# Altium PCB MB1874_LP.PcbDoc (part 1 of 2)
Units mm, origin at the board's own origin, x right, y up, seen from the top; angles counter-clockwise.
Board outline 59.8 x 34.35 mm, 2 copper layers (Top Layer, Bottom Layer), stack 0.78 mm thick; 77 components, 63 nets, 242 pads, 939 vias.
Unrouted connection lines stored in the file: 1.
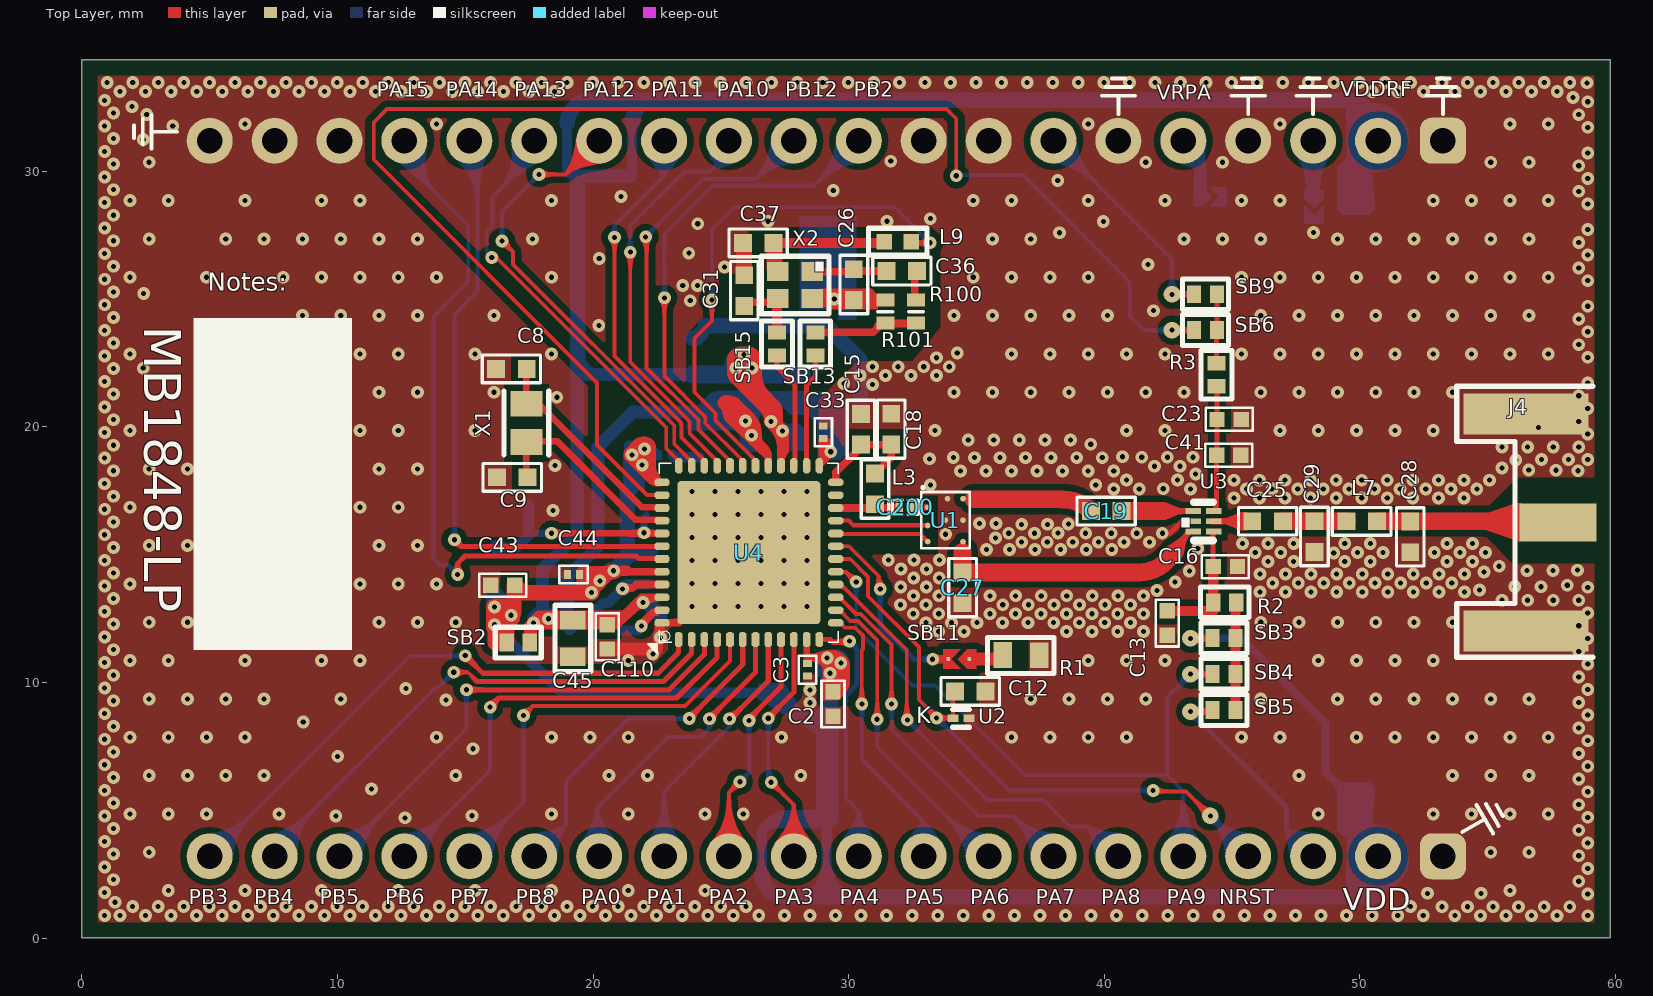
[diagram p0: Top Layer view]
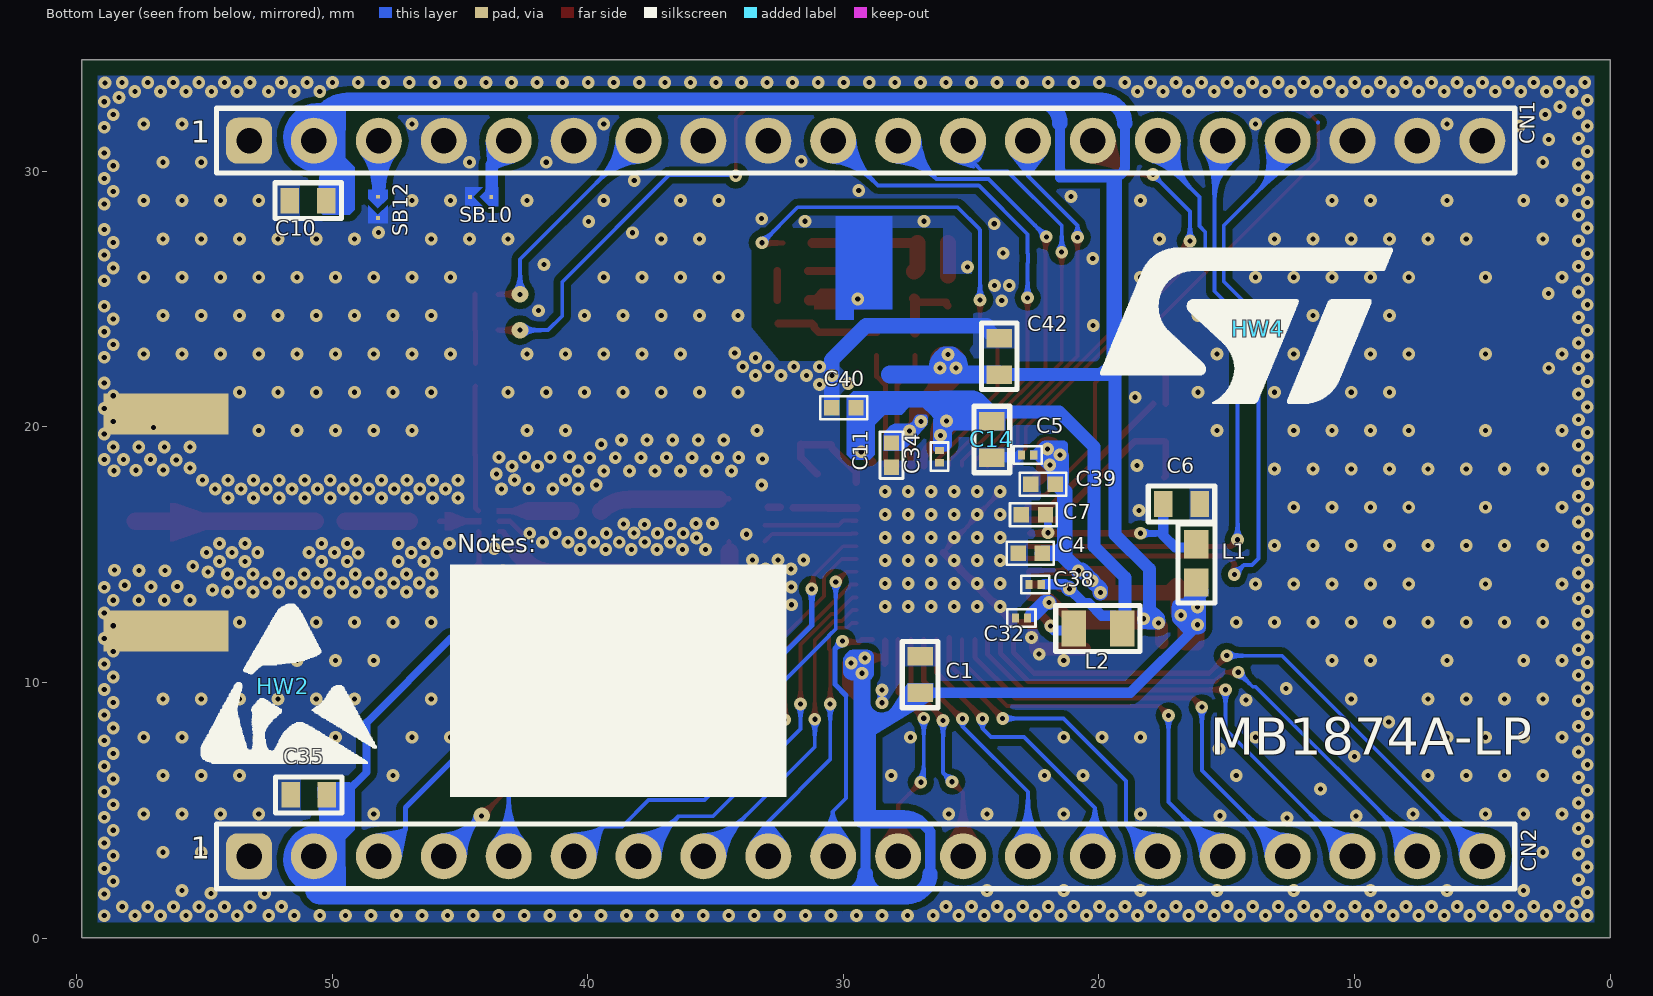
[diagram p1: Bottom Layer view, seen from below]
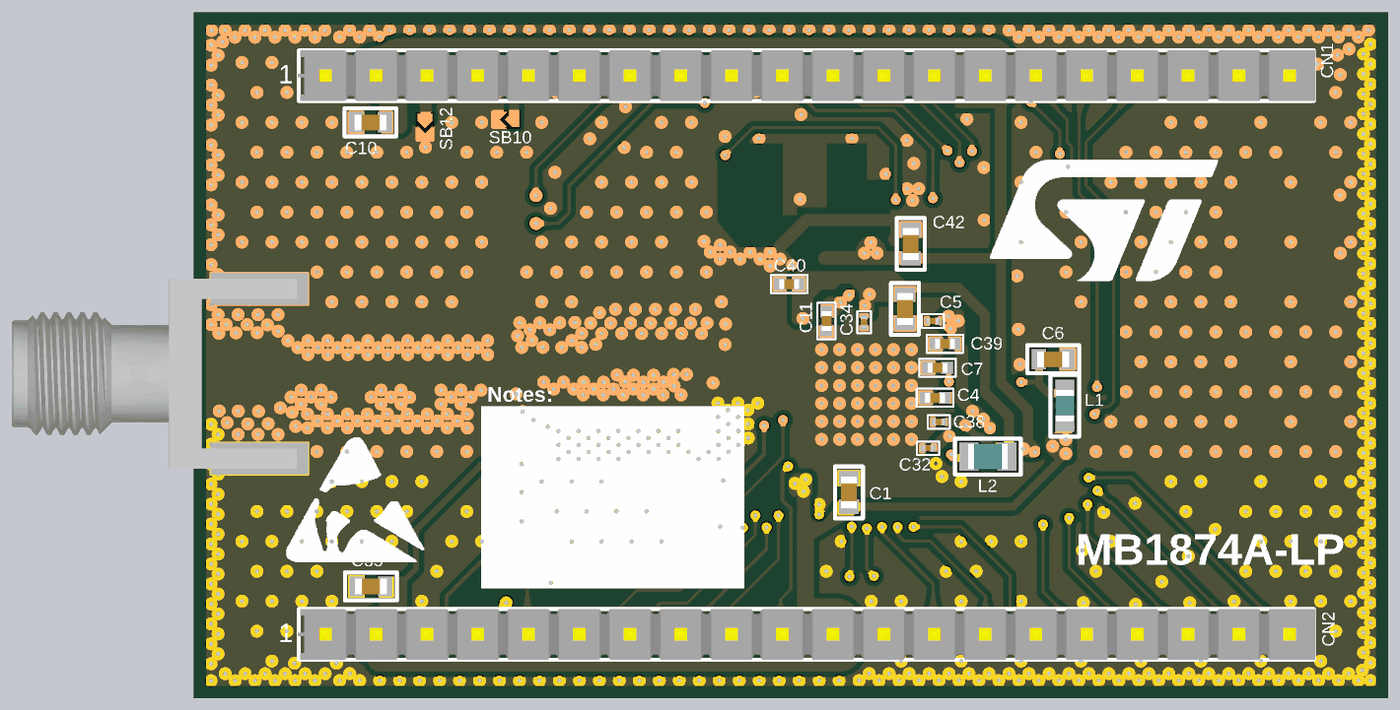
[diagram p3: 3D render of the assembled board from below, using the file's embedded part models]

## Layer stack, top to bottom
Top Solder: solder mask 0.03, Solder Resist, Dk 3.5
Top Layer: signal copper 0.035
Dielectric 1: core 0.71, FR-4, Dk 5
Bottom Layer: signal copper 0.035
Bottom Solder: solder mask 0.03, Solder Resist, Dk 3.5

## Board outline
0,0.009 0,34.363 59.8,34.363 59.8,0.009

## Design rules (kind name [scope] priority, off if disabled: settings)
BoardOutlineClearance [All and not (InComponent('J4', 'Target') or IsText)] p1: gap=0.6 ignorepadtopadclearanceinfootprint=FALSE
Clearance Clearance_Keepout [IsKeepout] p1: gap=0 ignorepadtopadclearanceinfootprint=FALSE
Clearance Clearance_GND_50ohm [InNetClass('50Ohm') vs InNamedPolygon('TOP_LAYER_GND')] p2: gap=0.25 ignorepadtopadclearanceinfootprint=FALSE except(0: Arc-Hole Track-Hole SMDPad-Hole THPad-Hole Via-Hole Fill-Hole Poly-Hole Region-Hole Text-Hole; 0.24: Arc-Fill Arc-Poly Arc-Region Track-Fill Track-Poly Track-Region)
Clearance Clearance_tab [(ObjectKind = 'Pad') And (Name Like 'Tab*-*') vs OnLayer('Keep-Out Layer')] p3: gap=0 ignorepadtopadclearanceinfootprint=FALSE
Clearance Clearance_Via_to_pad [IsVia vs IsPad] p4: gap=0.15 ignorepadtopadclearanceinfootprint=FALSE except(0: Arc-Hole Track-Hole SMDPad-Hole THPad-Hole Via-Hole Fill-Hole Poly-Hole Region-Hole Text-Hole)
Clearance Clearance_via_to_via [(ObjectKind = 'Via') And (Net <> 'GND') vs (ObjectKind = 'Via') And (Net <> 'GND')] p5: gap=0.25 ignorepadtopadclearanceinfootprint=FALSE except(0: Arc-Hole Track-Hole SMDPad-Hole THPad-Hole Via-Hole Fill-Hole Poly-Hole Region-Hole Text-Hole)
Clearance "Clearance_Polygon to All" [InPolygon] p6: gap=0.25 ignorepadtopadclearanceinfootprint=FALSE except(0: Arc-Hole Track-Hole SMDPad-Hole THPad-Hole Via-Hole Fill-Hole Poly-Hole Region-Hole Text-Hole)
Clearance [All] p7: gap=0.1 ignorepadtopadclearanceinfootprint=FALSE except(0: Arc-Hole Track-Hole SMDPad-Hole THPad-Hole Via-Hole Fill-Hole Poly-Hole Region-Hole Text-Hole)
ComponentClearance [All] p1 off: gap=0 collisioncheckmode=3 verticalgap=0.1 showdistances=FALSE
DiffPairsRouting [InDifferentialPair('RFI')] p1: maxlimit=0.1 minlimit=0.1 mostfreqgap=0.1 toplayer_minwidth=0.164 toplayer_maxwidth=0.164 toplayer_prefwidth=0.164 bottomlayer_minwidth=0.164 bottomlayer_maxwidth=0.164 bottomlayer_prefwidth=0.164 maxuncoupledlength=12.7
HoleSize [All] p1: absolutevalues=TRUE maxlimit=10 minlimit=0.025 maxpercent=80.000 minpercent=20.000
HoleToHoleClearance [All] p1: gap=0.25 allowstackedmicrovias=TRUE
MaximumViaCount MaximumViaCount_5 [InNet('GND')] p1: limit=1300
MaximumViaCount MaximumViaCount_4 [InNet('VDDRF1V55')] p2: limit=1000
MaximumViaCount MaximumViaCount_3 [InNet('VDDPA')] p3: limit=1000
MaximumViaCount MaximumViaCount_2 [InNet('VDDRF')] p4: limit=1000
MaximumViaCount MaximumViaCount_1 [InNet('VDD')] p5: limit=1000
MaximumViaCount [All] p6: limit=3
MinimumSolderMaskSliver [All] p1: minsoldermaskwidth=0.1
NetAntennae [All] p1 off: netantennaetolerance=0
PlaneConnect [InNet('GND')] p1: planeconnectstyle=Relief reliefexpansion=0.508 reliefentries=4 reliefconductorwidth=0.21 reliefairgap=0.21
PolygonConnect PolygonConnect_GND [InNet('GND') and not InComponent('J4')] p1: connectstyle=Direct reliefconductorwidth=0.254 reliefentries=4 polygonreliefangle="90 Angle" airgapwidth=0.254
PolygonConnect PolygonConnect_U1 [InComponent('U1')] p2: connectstyle=Direct reliefconductorwidth=0.254 reliefentries=4 polygonreliefangle="90 Angle" airgapwidth=0.254
PolygonConnect PolygonConnect_6 [InNet('VDDRF1V55')] p3: connectstyle=Direct reliefconductorwidth=0.254 reliefentries=4 polygonreliefangle="90 Angle" airgapwidth=0.254
PolygonConnect PolygonConnect_5 [InNet('VDDRF1V55')] p4: connectstyle=Direct reliefconductorwidth=0.254 reliefentries=4 polygonreliefangle="90 Angle" airgapwidth=0.254
PolygonConnect PolygonConnect_4 [InNet('vDDRF')] p5: connectstyle=Direct reliefconductorwidth=0.254 reliefentries=4 polygonreliefangle="90 Angle" airgapwidth=0.254
PolygonConnect PolygonConnect_3 [InNet('VDDPA')] p6: connectstyle=Direct reliefconductorwidth=0.254 reliefentries=4 polygonreliefangle="90 Angle" airgapwidth=0.254
PolygonConnect PolygonConnect_1 [InNet('VDDRF1V55')] p7: connectstyle=Direct reliefconductorwidth=0.254 reliefentries=4 polygonreliefangle="90 Angle" airgapwidth=0.254
PolygonConnect [InNet('VDD')] p8: connectstyle=Direct reliefconductorwidth=0.254 reliefentries=4 polygonreliefangle="90 Angle" airgapwidth=0.254
PolygonConnect PolygonConnect_All [All] p9: connectstyle=Relief reliefconductorwidth=0.254 reliefentries=4 polygonreliefangle="45 Angle" airgapwidth=0.254
RoutingLayers "RoutingLayers_90 Ohms" [InDifferentialPairClass('All Differential Pairs')] p1: top layer_v5=TRUE bottom layer_v5=TRUE
RoutingLayers [All] p2: top layer_v5=TRUE bottom layer_v5=TRUE
RoutingVias RoutingVias_BGA [InDrillLayerPair('Top Layer - MidLayer 1')] p1: holewidth=0.125 width=0.25 viastyle="Through Hole" minholewidth=0.125 minwidth=0.25 maxholewidth=0.125 maxwidth=0.3
RoutingVias [All] p2: holewidth=0.2 width=0.65 viastyle="Through Hole" minholewidth=0.2 minwidth=0.5 maxholewidth=0.2 maxwidth=0.7
ShortCircuit ShortCircuit_1 [IsPad and (Name = 'J4-2') vs IsVia and InNet('GND')] p1: allowed=TRUE
ShortCircuit ShortCircuit_U4 [IsPad and (Name = 'U4-49') vs IsVia and InNet('GND')] p2: allowed=TRUE
ShortCircuit [(ObjectKind = 'Via') And (DrillPair = 'Top Layer - MidLayer 1') vs Ispad] p3: allowed=TRUE
SilkToSilkClearance [All] p1: silktosilkclearance=0.08
SilkToSolderMaskClearance [IsPad] p1: minsilkscreentomaskgap=0.05 clearancetoexposedcopper=TRUE
SolderMaskExpansion SolderMaskExpansion_VIA [IsVia] p1: expansion=-0.2 istentingtop=FALSE
SolderMaskExpansion [All] p2: expansion=0.075 istentingtop=FALSE
Width Width_50Ohms [InNetClass('50Ohm')] p1: maxlimit=0.7 minlimit=0.2 preferedwidth=0.7 minimp=50.000000 maximp=50.000000 favimp=50.000000
Width [All] p2: maxlimit=1.5 minlimit=0.1 preferedwidth=0.15 minimp=50.000000 maximp=50.000000 favimp=50.000000
19 further rules are at their usual default settings.

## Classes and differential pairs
component class MB1874A: C1 C2 C3 C4 C5 C6 C7 C8 C9 C10 C11 C12 C13 C14 C15 C16 C18 C19 C23 C25 C26 C27 C28 C29 C31 C32 C33 C34 C35 C36 C37 C38 C39 C40 C41 C42 C43 C44 C45 C110 CN1 CN2 J4 L1 L2 L3 L7 L9 R1 R2 R3 R100 R101 S1 SB2 SB3 SB4 SB5 SB6 SB9 SB10 SB11 SB12 SB13 SB15 U2 U3 U4 X1 X2
net class 50ohm: NetC19_1 NetC19_2 NetC25_1 NetC25_2 NetC27_2 NetC28_1
differential pair RFI: +RFI_P -RFI_N

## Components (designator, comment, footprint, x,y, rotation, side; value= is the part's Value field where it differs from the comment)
C1 "" CAPC1608X09N 26.998,10.311 r270 bottom
C2 "" CAPC1005X06N 29.391,9.159 r90 top
C3 "" 0201 28.391,10.259 r90 top
C4 "" CAPC1005X06N 22.691,15.059 r180 bottom
C5 "" 0201 23.034,18.898 r180 bottom
C6 "" CAPC1608X09N 16.771,16.986 r180 bottom
C7 "" CAPC1005X06N 22.566,16.559 r0 bottom
C8 "Capacitor" 0402 17.405,22.273 r180 top
C9 "Capacitor" 0402 17.44,18.03 r180 top
C10 "" CAPC1608X09N 50.949,28.855 r0 bottom
C11 "" CAPC1005X06N 28.12,18.9 r270 bottom
C12 "" 0402 34.165,9.65 r0 top
C13 "" CAPC1005X06N 42.469,12.326 r90 top
C14 "" CAPC1608X09N 24.191,19.509 r270 bottom
C15 "" 0402 30.487,19.309 r90 top
C16 "" CAPC1005X06N 44.742,14.537 r180 top
C18 "" 0402 31.672,20.514 r270 top
C19 "" 0402 40.678,16.709 r180 top
C23 "" CAPC1005X06N 44.893,20.293 r180 top
C25 "" 0402_2 45.764,16.309 r0 top
C26 "Capacitor" 0402 30.205,26.171 r270 top
C27 "NC" 0402_2 34.464,13.078 r90 top
C28 "MCD-00102" 0402 51.979,16.294 r270 top
C29 "MCD-00102" 0402 48.226,16.309 r270 top
C31 "Capacitor" 0402 25.918,24.738 r90 top
C32 "" 0201 23.273,12.523 r180 bottom
C33 "" 0201 29.01,20.032 r270 top
C34 "" 0201 26.239,18.601 r90 bottom
C35 "" CAPC1608X09N 50.923,5.601 r180 bottom
C36 "" 0402 32.683,26.1 r180 top
C37 "" 0402 25.865,27.2 r0 top
C38 "" 0201 22.26,13.84 r0 bottom
C39 "" CAPC1005X06N 22.191,17.759 r0 bottom
C40 "" CAPC1005X06N 29.987,20.756 r0 bottom
C41 "" CAPC1005X06N 44.878,18.893 r0 top
C42 "" CAPC1608X09N 23.904,22.761 r90 bottom
C43 "" CAPC1005X06N 16.468,13.811 r0 top
C44 "" 0201 18.997,14.231 r0 top
C45 "" CAPC1608X09N 19.211,11.724 r270 top
C110 "" CAPC1005X06N 20.561,11.788 r270 top
C200 "MCD-00198" 0201 32.463,16.857 r180 top
CN1 "CON20" CO_SAMTEC_TSW-120-07-X-S 29.13,31.2 r180 bottom
CN2 "CON20" CO_SAMTEC_TSW-120-07-X-S 29.13,3.2 r180 bottom
Designator16 "Comment" IMPEDANCE_TABLE 100.43,-31.664 r0 top
HW2 "Logo" LOGO_MAIN 51.913,9.844 r180 bottom
HW4 "Logo" LOGO_ST 13.76,23.849 r180 bottom
J4 "SMA_T_9.52_NF" SMA_AMPHENOL_50ohms_Edge_PCB 59.264,16.261 r90 top
L1 "" INDC1608X95N 16.191,14.659 r90 bottom
L2 "" INDC2012X13N 20.041,12.109 r0 bottom
L3 "" 0402_COIL 31.037,17.573 r270 top
L7 "" 0402_COIL 50.079,16.309 r0 top
L9 "ferrite" IND_MURATA_LQW15A 31.93,27.25 r0 top
R1 "" RESC1608X05N 36.741,11.059 r180 top
R2 "" RESC1005X04N 44.72,13.138 r0 top
R3 "" RESC1005X04N 44.398,22.043 r90 top
R100 "Resistor" R0402 32.641,24.509 r90 top
R101 "Resistor" R0402 31.441,24.509 r90 top
SB2 "Close" SB_0402 17.075,11.561 r180 top
SB3 "Close" SB_0402 44.688,11.737 r0 top
SB4 "Open" SB_0402 44.688,10.337 r0 top
SB5 "Open" SB_0402 44.688,8.923 r0 top
SB6 "Close" SB_0402 43.961,23.794 r0 top
SB9 "Open" SB_0402 43.961,25.194 r0 top
SB10 "Open" GC_0402 44.158,29.005 r0 bottom
SB11 "Close" GC_0402 34.35,10.919 r180 top
SB12 "Open" GC_0402 48.216,28.631 r270 bottom
SB13 "Close" SB_0402 28.7,23.25 r90 top
SB15 "Close" SB_0402 27.2,23.25 r90 top
Target "" "Target PCB" -9,-9 r90 top
Target "" "Target PCB" 74,17.2 r90 top
Target "" "Target PCB" -9,43 r90 top
U1 "IPD STM STM32WL" "IPD STM" 33.788,16.354 r180 top
U2 "" DIOM0603X03N 34.4,8.6 r0 top
U3 "BGS12SN6" SON40P70X40-6N 43.884,16.309 r0 top
U4 "STM32WLxx_QFN48" STM32WLXX_QFN48 26.097,15.083 r90 top
X1 "XTAL_2_PINS" OSC_NDK_NX2012SA 17.395,20.162 r90 top
X2 "" OSC_NDK_NX2016SA 27.91,25.553 r180 top

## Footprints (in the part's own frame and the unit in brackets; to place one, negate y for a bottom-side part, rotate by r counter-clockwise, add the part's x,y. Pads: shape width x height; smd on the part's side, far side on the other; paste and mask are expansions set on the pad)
0201 [mm]
  rect 0.28x0.35 smd: 1(0,0) 2(0.48,0)
  silkscreen extent -0.31,-0.34 0.79,0.34, body extent -0.06,-0.15 0.54,0.15, height 0.3
0402 [mm] "Chip Capacitor, Body 1.0x0.5mm, IPC High Density"
  rect 0.7x0.7 smd: 1(-0.001,0) 2(1.197,0)
  silkscreen extent -0.54,-0.54 1.74,0.54, body extent -0.42,-0.36 1.62,0.36, height 0.82
0402_2 [mm]
  rect 0.7x0.7 smd: 1(0.035,0) 2(1.233,0)
  silkscreen extent -0.51,-0.54 1.78,0.54, body extent -0.38,-0.36 1.65,0.36, height 0.82
0402_COIL [mm] "Coil FootPrint 0402"
  rect 0.7x0.7 smd: 1(-0.599,0) 2(0.599,0)
  silkscreen extent -1.15,-0.54 1.14,0.54, body extent -0.5,-0.3 0.5,0.3, height 0.51
CAPC1005X06N [mm]
  rect 0.6x0.6 smd: 1(-0.475,0) 2(0.475,0)
  silkscreen extent -0.92,-0.45 0.92,0.45, body extent -0.5,-0.25 0.5,0.25, height 0.6
CAPC1608X09N [mm]
  rect 0.725x1 smd: 1(-0.713,0) 2(0.713,0)
  Top Layer pour cut-out: -0.3,0.7 0.3,0.7 0.3,-0.7 -0.3,-0.7
  silkscreen extent -1.3,-0.7 1.3,0.7, body extent -0.8,-0.4 0.8,0.4, height 0.9
CO_SAMTEC_TSW-120-07-X-S [mm] "Header, 20-Leads, 50.80x2.54x10.80mm, Pitch 2.54mm"
  rrect50% 1.8x1.8 hole 1: 1(-24.13,0)
  round 1.8 hole 1: 2(-21.59,0) 3(-19.05,0) 4(-16.51,0) 5(-13.97,0) 6(-11.43,0) 7(-8.89,0) 8(-6.35,0) 9(-3.81,0) 10(-1.27,0) 11(1.27,0) 12(3.81,0) 13(6.35,0) 14(8.89,0) 15(11.43,0) 16(13.97,0) 17(16.51,0) 18(19.05,0) 19(21.59,0) 20(24.13,0)
  silkscreen extent -25.4,-1.27 25.4,1.27, body extent -25.46,-1.27 25.46,1.27, height 8.38
DIOM0603X03N [mm] "Molded Diode, 2-Leads, Body 0.60x0.30mm"
  rect 0.425x0.3 smd: 1(-0.312,0) 2(0.313,0)
  silkscreen extent -0.32,-0.35 0.33,0.35, body extent -0.32,-0.18 0.33,0.18, height 0.33
GC_0402 [mm] "Grain de café format 0402"
  rect 0.15x0.15 smd paste-1: 1(-0.375,0) 2(0.45,0)
  Top Layer region: -0.05,0.375 0.65,0.375 0.65,-0.375 -0.05,-0.375 0.325,0
  Top Layer region: -0.65,0.375 -0.3,0.375 0.075,0 -0.3,-0.375 -0.65,-0.375
  body extent -0.5,-0.25 0.6,0.25, height 0.2
IMPEDANCE_TABLE [mm]
IND_MURATA_LQW15A [mm] "Inductor 2-Leads,Body 1.10x0.70x0.60mm(max)"
  rect 0.6x0.6 smd: 1(-0.53,0) 2(0.53,0)
  silkscreen extent -1.14,-0.53 1.14,0.53, body extent -0.5,-0.3 0.5,0.3, height 0.51
INDC1608X95N [mm] "Chip Inductor, 2-Leads, Body 1.75x0.95x0.95mm (0603)"
  rect 1.1x0.95 smd: 1(-0.75,0) 2(0.75,0)
  silkscreen extent -1.55,-0.72 1.55,0.72, body extent -0.8,-0.48 0.8,0.47, height 0.8
INDC2012X13N [mm] "Chip Inductor, 2-Leads, Body 2.0x1.2x1.3 (0805)"
  rect 0.96x1.4 smd: 1(-0.952,0) 2(0.952,0)
  silkscreen extent -1.65,-0.9 1.65,0.9, body extent -1,-0.65 1,0.65, height 1.18
"IPD STM" [mm] "IPD STM STM32WL, Body 2.20 x 1.90 x 0.710 mm (LxWxH max)"
  round 0.22 smd mask+0.05: 1(0.69,-0.5) 2(0.69,0.84) 3(0.69,0.21) 4(-0.69,0.84) 5(-0.69,0) 6(-0.69,-0.84) 7(-0.085,-0.84) 8(0,0)
  silkscreen extent -0.95,-1.33 0.95,1.1, body extent -0.84,-1 0.84,1, height 0.71
LOGO_MAIN [mm]
  silkscreen extent -3.24,-3.02 3.65,3.22
LOGO_ST [mm]
  silkscreen extent -6.18,-2.95 5.25,3.14
OSC_NDK_NX2012SA [mm] "Crystal, 2-Leads, Body 2.05x1.20x0.55mm (Tol:-/+0.05)"
  rect 1x1.25 smd: 1(-0.75,0) 2(0.75,0)
  silkscreen extent -1.25,-0.87 1.25,0.87, body extent -1.04,-0.63 1.03,0.63, height 0.55
OSC_NDK_NX2016SA [mm] "Crystal, 4-Leads, Body 2.10x1.61x0.50mm (max), Pitch 1.35x1.05mm"
  rect 0.85x0.75 smd: 1(-0.675,-0.525) 2(0.675,-0.525) 3(0.675,0.525) 4(-0.675,0.525)
  silkscreen extent -1.33,-1.12 1.33,1.13, body extent -1,-0.8 1,0.8, height 0.5
R0402 [mm]
  rect 0.51x0.7 smd mask+0.05: 1(-0.45,0) 2(0.45,0)
  silkscreen extent 0,-0.3 0,0.3, body extent -0.52,-0.3 0.52,0.3, height 0.4
RESC1005X04N [mm] "Chip Resistor, 2-Leads, Body 1.00x0.50mm (0402)"
  rect 0.55x0.7 smd: 1(-0.45,0) 2(0.45,0)
  silkscreen extent -0.95,-0.6 0.95,0.6, body extent -0.5,-0.25 0.5,0.25, height 0.35
RESC1608X05N [mm] "Chip Resistor, 2-Leads, Body 1.60x0.80mm (0603)"
  rect 0.725x1 smd: 1(-0.713,0) 2(0.712,-0.016)
  Top Layer pour cut-out: -0.3,0.7 0.3,0.7 0.3,-0.7 -0.3,-0.7
  silkscreen extent -1.3,-0.7 1.3,0.7, body extent -0.77,-0.42 0.78,0.43, height 0.45
SB_0402 [mm]
  rect 0.55x0.7 smd: 1(-0.45,0) 2(0.45,0)
  silkscreen extent -0.9,-0.6 0.9,0.6, body extent -0.5,-0.25 0.5,0.25, height 0.25
SMA_AMPHENOL_50ohms_Edge_PCB [mm] "RF Connector, SMA End Launch Jack for 0.047 inch (1.19 mm thickness) PCB, 50 Ohm, Flat Tab Contact"
  rect 1.5x3 smd mask+0.05: 1(0,1.5)
  rect 1.6x4.9 smd mask+0.05: 2(-4.25,2.75) 2(4.25,2.75)
  rect 1.6x4.9 smd far side mask+0.05: 2(-4.25,2.75) 2(4.25,2.75)
  silkscreen extent -5.27,0.13 5.33,5.47, body extent -4.76,-9.65 4.76,4.62, height 4.09
SON40P70X40-6N [mm] "SON, 6-Leads, Body 1.10x0.70mm, Pitch 0.40mm"
  rect 0.6x0.225 smd: 1(-0.4,0.4) 2(-0.4,0) 3(-0.4,-0.4) 4(0.4,-0.4) 5(0.4,0) 6(0.4,0.4)
  silkscreen extent -0.38,-0.75 0.38,0.75, body extent -0.38,-0.58 0.38,0.58, height 0.4
STM32WLXX_QFN48 [mm] "QFN48 7x7x0.55mm pitch 0.5mm"
  oct 0.6x0.3 smd mask+0.06: 1(-3.398,2.746) 2(-3.398,2.239) 3(-3.398,1.739) 4(-3.398,1.239) 5(-3.398,0.739) 6(-3.398,0.239) 7(-3.398,-0.261) 8(-3.398,-0.761) 9(-3.398,-1.261) 10(-3.398,-1.761) 11(-3.398,-2.261) 12(-3.398,-2.761) 25(3.398,-2.761) 26(3.398,-2.261) 27(3.398,-1.761) 28(3.398,-1.261) 29(3.398,-0.761) 30(3.398,-0.261) 31(3.398,0.239) 32(3.398,0.739) 33(3.398,1.239) 34(3.398,1.739) 35(3.398,2.239) 36(3.398,2.739)
  oct 0.3x0.6 smd mask+0.06: 13(-2.752,-3.399) 14(-2.252,-3.399) 15(-1.752,-3.399) 16(-1.252,-3.399) 17(-0.752,-3.399) 18(-0.252,-3.399) 19(0.248,-3.399) 20(0.748,-3.399) 21(1.248,-3.399) 22(1.748,-3.399) 23(2.248,-3.399) 24(2.748,-3.399) 37(2.748,3.399) 38(2.248,3.399) 39(1.748,3.399) 40(1.248,3.399) 41(0.748,3.399) 42(0.248,3.399) 43(-0.252,3.399) 44(-0.752,3.399) 45(-1.252,3.399) 46(-1.752,3.399) 47(-2.252,3.399) 48(-2.752,3.399)
  rrect5% 5.6x5.6 smd paste-3 mask+0.08: 49(0,0)
  silkscreen extent -3.95,-3.5 3.5,3.96, body extent -3.51,-3.51 3.51,3.51, height 0.78
"Target PCB" [mm] "TargetA"

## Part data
C1 C6 C10 C35 C42 C45: library part MCD-00009, "Capacitor, MLCC, 4.7uF, 16V, X5R, 10%, 0603, T=0.8mm"
C2 C4 C7 C11 C12 C39 C40 C43 C110: library part MCD-00102, "Capacitor, MLCC, 100nF, 16V, X7R, 10%, 0402, T=0,5mm"
C3 C5 C44: library part MCD-00102, "Multilayer Ceramic Capacitors MLCC - SMD/SMT 0201 25VDC 0.1uF 10% X5R 0.3mm"
C8 C9 C26 C31: library part MCD-00003, "Capacitor, MLCC, 6.8pF, 50V, NPO, +-0.1pF, 0402, T=0.5mm"
C13 C23: library part MCD-00198, "Capacitor, MLCC, 1nF, 16V, X7R, 10%, 0402, T=0.5mm"
C14: library part MCD-00009, "Capacitor, MLCC, 0.47 uF, 16V, X5R, 10%, 0603, T=0.8mm"
C15: library part MCD-01123, "Capacitor, MLCC,47nF, 25V, X7R, 10%, 0402, T=0.5mm"
C16 C41: library part MCD-00102, "Capacitor, MLCC, 10 pF"
C18: library part MCD-01123, "Capacitor, MLCC,68pF, 50V, C0G, 1%, 0402, T=0.5mm"
C19: library part MCD-01123, "Condensateurs céramique multicouches MLCC - CMS 33PF 50V 2% 0402"
C25: library part MCD-01123, "Multilayer Ceramic Capacitors MLCC - SMD/SMT 0402 68pF 50volts C0G 5%"
C27: library part MCD-01123, "Not connected [0402]"
C28 C29: "Condensateurs céramique multicouches MLCC - CMS 0402 3.3pF 50Volts C0G +/-0.05pF"
C32 C33 C34: library part MCD-00277, "Multilayer Ceramic Capacitors MLCC - SMD/SMT 0201 33pF 25volts C0G 5%"
C36 C37: library part MCD-00277, "Capacitor, MLCC, 33pF, 50V, NPO, 2%, 0402, T=0,5mm"
C38: library part MCD-01123, "Multilayer Ceramic Capacitors MLCC - SMD/SMT 0201 33pF 25volts C0G 5%"
C200: "Multilayer ceramic capacitors COG +/-5%, 50V"
CN1 CN2: "Connector right-angle, pitch 2.54mm, 20 contacts"
Designator16: library part MCD-00279
HW2: library part MCD-00627, "\"Hand\" ESD logo footprint for PCB"
HW4: library part MCD-00625, "\"STMicroelectronics\" logo footprint for PCB"
J4: "SMA Jack, Edge Mount, 50 Ohms"
L1: library part MCD-00047, "SMD Chip ferrite bead, 600R@100MHz +/-25%, 350mA, 500mohm DC, 0603, T=0.8mm"
L2: library part MCD-01433, "MLZ2012 Multilayer Shielded Inductor 15 uH, ±5%"
L3: library part MCD-01330, "Inductor, 68nH, +-0.1nH, 140mA, 0402"
L7: library part MCD-01330, "Inductor, 15nH, +-0.1nH, 640mA, 0402"
L9: library part MCD-01330, "Inductor, 3.9nH, +-0.1nH, 750mA, 0402"
R1: library part MCD-00220, "Resistor,10K,0603,1%,1/10W"
R2 R3: library part MCD-00119, "Resistor,100R,0402,1%,1/16W"
R100 R101: library part MCD-00052, "Resistor,0R,0402,5%,1/16W"
SB2 SB4 SB5 SB9: library part SB_Open, "Solder Bridge Open [0402] (Unpopulated)"
SB3 SB6 SB13 SB15: library part SB_0Ohm, "Solder Bridge 0R [0402] (Populated with 0 Ohm)"
SB10 SB12: library part Strap2, "Solder Jumper - Open"
SB11: library part Strap2, "Solder Jumper - Close"
U1: library part "IPD ST STM32WL"
U2: library part MCD-00170, "ESD protection 6V1"
U3: "DC switch - Ultra-Low  SPDT analog switch"
U4: "STM32WL ARM MCU Multiprotocol LPWAN 32-bit Arm Cortex-M4 MCUs LoRa (G)FSK-MSK BPSK"
X1: library part MCD-01479, "Crystal 32.768kHz, 6pF, -+20PPM, R=80K, SMD"
X2: library part MCD-01446, "Crystal 32 MHz, 8pF, -+10 PPM, R=60O, SMD"

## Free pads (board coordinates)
  round 0.508 on Mech16: 1(20.921,-21.528) 1(69.938,-26.528)

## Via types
v1: diameter 0.5, hole 0.2, Top Layer to Bottom Layer, 933 vias
v2: diameter 0.65, hole 0.2, Top Layer to Bottom Layer, 6 vias

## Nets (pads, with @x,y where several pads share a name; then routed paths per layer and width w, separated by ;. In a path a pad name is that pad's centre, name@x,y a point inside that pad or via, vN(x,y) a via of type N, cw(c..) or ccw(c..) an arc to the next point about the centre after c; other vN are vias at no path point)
FE_CTRL2: CN1.7 SB9.1 | length 8.8
  Top Layer w0.2: v2(42.658,25.189) SB9.1@43.506,25.189
  Bottom Layer w0.15: CN1.7@38.02,31.2 42.658,26.562 v2(42.658,25.189)
FE_CTRL3: CN2.3 SB5.1 | length 8.5
  Top Layer w0.2: v2(43.381,8.859) 44.175,8.859 SB5.1@44.238,8.923
  Bottom Layer w0.2: v2(43.381,8.859) 47.137,5.104 47.137,4.243 CN2.3@48.18,3.2
GND: C1.1 C2.1 C3.1 C4.1 C5.1 C6.2 C7.2 C8.2 C9.2 C10.2 C11.2 C12.2 C13.1 C14.2 C15.2 C16.1 C18.1 C23.1 C26.2 C27.1 C28.2 C29.2 C31.2 C32.1 C33.1 C34.1 C35.1 C37.1 C38.2 C39.2 C40.2 C41.2 C42.2 C43.1 C44.1 C45.2 C110.2 CN1.1 CN1.4 CN1.6 CN1.8 CN1.9 CN1.18 CN1.19 CN1.20 CN2.1 J4.2 R1.1 R101.2 SB10.2 SB12.2 U1.5 U1.7 U1.8 U2.2 U3.2 U4.48 U4.49 X2.4 | length 26.7
  Top Layer w0.15: v1(23.867,17.47) 24.736,16.541 25.604,15.611 U4.49@26.097,15.083
  Top Layer w0.2: 22.463,11.337 22.54,11.413 ; U4.48@22.698,12.332 U4.48@22.769,12.332 ; 42.577,15.84 43.046,16.309 U3.2@43.484,16.309
  Top Layer w0.3: U4.48@22.769,12.332 23.345,12.332 U4.49@26.097,15.083
  Top Layer w0.4: v1@22.463,11.29 22.54,11.367 22.54,11.413 22.54,11.88 22.6,11.94 U4.48@22.6,12.232 ; X2.4@28.585,25.028 28.594,25.019 29.432,25.019 v1(29.441,25.009) ; C26.2@30.205,24.974 30.219,24.959 R101.2@31.341,24.959
  Top Layer w0.5: C110.2@20.561,11.313 22.441,11.313 v1@22.463,11.29
  Top Layer w0.625: C37.1@25.9,27.2 25.918,27.182 C31.2@25.917,25.935 ; 29.765,25.028 29.855,24.938
  Bottom Layer w0.2: v1@28.49,9.264 28.49,9.784 v1@28.53,9.824
  Bottom Layer w0.4: C5.1@23.111,18.909 23.202,18.818 C14.2@24.166,18.818 ; C42.2@23.904,23.474 24.392,23.962 ; C40.2@30.462,20.756 C40.2@30.491,20.727
  Bottom Layer w0.6: C42.2@23.904,23.474 24.041,23.474 C42.2@24.268,23.7 ; 24.392,23.962 29.12,23.962 30.462,22.62 C40.2@30.462,20.756
  other v1: 0.89,0.88 1.49,0.88 2.49,0.88 3.49,0.88 4.49,0.88 5.49,0.88 6.49,0.88 7.49,0.88 8.49,0.88 9.49,0.88 10.49,0.88 11.49,0.88 12.49,0.88 13.49,0.88 14.49,0.88 15.49,0.88 16.49,0.88 17.49,0.88 18.49,0.88 19.49,0.88 20.49,0.88 21.49,0.88 22.49,0.88 23.49,0.88 24.49,0.88 25.49,0.88 26.49,0.88 27.49,0.88 28.49,0.88 29.49,0.88 30.49,0.88 31.49,0.88 32.49,0.88 33.49,0.88 34.49,0.88 35.49,0.88 36.49,0.88 37.49,0.88 38.49,0.88 39.49,0.88 40.49,0.88 41.49,0.88 42.49,0.88 43.49,0.88 44.49,0.88 45.49,0.88 46.49,0.88 47.49,0.88 48.49,0.88 49.49,0.88 50.49,0.88 51.49,0.88 52.49,0.88 53.725,0.875 54.725,0.875 55.725,0.875 56.725,0.875 57.725,0.875 58.925,0.875 1.985,1.23 2.985,1.23 3.985,1.23 4.985,1.23 5.985,1.23 6.985,1.23 7.985,1.23 8.985,1.23 9.985,1.23 10.985,1.23 11.985,1.23 12.985,1.23 13.985,1.23 14.985,1.23 15.985,1.23 16.985,1.23 17.985,1.23 18.985,1.23 19.985,1.23 20.985,1.23 21.985,1.23 22.985,1.23 23.985,1.23 24.985,1.23 25.985,1.23 51.985,1.23 53.221,1.225 54.221,1.225 55.221,1.225 56.221,1.225 57.221,1.225 58.221,1.225 1.3,1.4 58.925,1.725 52.65,1.75 54.75,1.75 0.89,1.78 3.381,1.858 6.381,1.858 9.381,1.858 12.381,1.858 15.381,1.858 18.381,1.858 21.381,1.858 24.381,1.858 55.881,1.858 58.575,2.221 1.239,2.284 58.925,2.725 0.89,2.78 58.575,3.221 1.239,3.284 2.631,3.358 55.131,3.358 56.631,3.358 58.925,3.725 0.89,3.78 58.575,4.221 1.239,4.284 12.648,4.704 58.925,4.725 9.936,4.775 0.89,4.78 15.262,4.784 1.881,4.858 3.381,4.858 4.881,4.858 7.717,4.856 18.381,4.858 21.381,4.858 24.381,4.858 25.881,4.858 48.381,4.858 52.881,4.858 54.381,4.858 55.881,4.858 57.381,4.858 58.575,5.221 1.239,5.284 58.925,5.725 0.89,5.78 11.337,5.835 58.575,6.221 1.239,6.284 2.631,6.358 4.131,6.358 5.631,6.358 7.131,6.358 14.631,6.358 20.631,6.358 22.131,6.358 28.131,6.358 47.631,6.358 53.631,6.358 55.131,6.358 56.631,6.358 58.925,6.725 0.89,6.78 10.008,7.111 58.575,7.221 1.239,7.284 15.307,7.407 58.925,7.725 0.89,7.78 1.881,7.858 3.381,7.858 4.881,7.858 6.381,7.858 13.881,7.858 18.381,7.858 19.881,7.858 21.381,7.858 27.381,7.858 36.381,7.858 37.881,7.858 39.381,7.858 40.881,7.858 45.381,7.858 46.881,7.858 49.881,7.858 51.381,7.858 52.881,7.858 54.381,7.858 55.881,7.858 57.381,7.858 58.575,8.221 1.239,8.284 8.66,8.458 58.925,8.725 0.89,8.78 28.491,9.209 58.575,9.221 1.239,9.284 14.247,9.311 2.631,9.358 4.131,9.358 5.631,9.358 7.131,9.358 10.131,9.358 37.131,9.358 38.631,9.358 40.131,9.358 41.631,9.358 46.131,9.358 49.131,9.358 50.631,9.358 52.131,9.358 53.631,9.358 55.131,9.358 56.631,9.358 28.491,9.709 58.925,9.725 0.89,9.78 12.675,9.769 58.575,10.221 1.239,10.284 58.925,10.725 0.89,10.78 1.881,10.858 3.381,10.858 6.381,10.858 9.381,10.858 10.881,10.858 21.381,10.858 39.381,10.858 40.881,10.858 42.381,10.858 48.381,10.858 49.881,10.858 51.381,10.858 52.881,10.858 22.341,11.109 58.575,11.221 1.239,11.284 58.925,11.725 22.641,11.759 0.89,11.78 33.523,11.992 34.523,11.992 38.531,11.992 39.531,11.992 40.531,11.992 41.54,11.992 58.575,12.221 1.239,12.284 33.027,12.342 34.027,12.342 35.027,12.342 36.027,12.342 37.027,12.342 38.027,12.342 39.027,12.342 40.027,12.342 41.036,12.342 2.631,12.358 4.131,12.358 5.631,12.358 7.131,12.358 8.631,12.358 10.131,12.358 11.631,12.358 13.131,12.358 14.631,12.358 46.131,12.358 47.631,12.358 49.131,12.358 50.631,12.358 52.131,12.358 53.631,12.358 32.531,12.691 33.531,12.691 35.531,12.691 36.531,12.691 37.531,12.691 38.531,12.691 39.531,12.691 40.531,12.691 41.54,12.691 58.925,12.725 0.89,12.78 23.867,12.97 24.767,12.97 25.667,12.97 26.567,12.97 27.467,12.97 28.367,12.97 32.036,13.041 33.036,13.041 36.036,13.041 37.036,13.041 38.036,13.041 39.036,13.041 40.036,13.041 41.036,13.041 55.575,13.221 56.575,13.221 57.575,13.221 58.575,13.221 1.239,13.284 32.54,13.391 33.54,13.391 35.54,13.391 36.54,13.391 37.54,13.391 38.54,13.391 39.54,13.391 40.54,13.391 41.54,13.391 46.1,13.542 47.1,13.542 48.1,13.542 49.1,13.542 50.1,13.542 51.1,13.542 52.101,13.542 53.1,13.542 54.1,13.542 42.075,13.6 54.694,13.619 32.044,13.74 33.044,13.74 58.925,13.725 56.067,13.758 57.091,13.748 0.89,13.78 58.124,13.806 1.881,13.858 4.881,13.858 7.881,13.858 9.381,13.858 10.881,13.858 12.381,13.858 13.881,13.858 23.867,13.87 24.767,13.87 25.667,13.87 26.567,13.87 27.467,13.87 28.367,13.87 46.596,13.892 47.596,13.892 48.596,13.892 49.596,13.892 50.596,13.892 51.605,13.892 52.605,13.892 53.605,13.892 42.782,13.93 32.549,14.09 33.549,14.09 46.1,14.242 47.1,14.242 48.1,14.242 49.1,14.242 50.1,14.242 51.1,14.242 52.101,14.242 53.1,14.242 54.1,14.242 1.239,14.284 54.87,14.328 43.335,14.362 56.55,14.376 57.564,14.385 58.52,14.395 32.053,14.44 33.053,14.44 55.459,14.55 46.417,14.739 47.417,14.739 49.417,14.739 50.417,14.739 53.417,14.739 54.417,14.739 0.89,14.78 23.867,14.77 24.767,14.77 25.667,14.77 26.567,14.77 27.467,14.77 28.367,14.77 31.557,14.789 32.557,14.789 33.557,14.789 45.913,15.089 46.913,15.089 48.985,15.069 49.913,15.089 50.913,15.089 52.922,15.089 53.922,15.089 54.922,15.089 35.4,15.2 36.3,15.2 37.3,15.2 38.3,15.2 39.3,15.2 40.3,15.2 43.663,15.248 1.239,15.284 2.631,15.358 4.131,15.358 5.631,15.358 7.131,15.358 8.631,15.358 10.131,15.358 11.631,15.358 13.131,15.358 45.417,15.438 46.417,15.438 47.417,15.438 49.417,15.438 50.417,15.438 53.417,15.438 54.417,15.438 36.775,15.491 37.775,15.491 38.775,15.491 39.775,15.491 40.775,15.491 41.775,15.491 23.867,15.67 24.767,15.67 25.667,15.67 26.567,15.67 27.467,15.67 28.367,15.67 35.75,15.65 0.89,15.78 33.8,15.8 36.27,15.84 37.279,15.84 38.2,15.85 39.279,15.84 40.279,15.84 41.279,15.84 42.279,15.84 36.775,16.19 37.783,16.19 38.6,16.2 35.125,16.225 35.775,16.225 1.239,16.284 23.867,16.57 24.767,16.57 25.667,16.57 26.567,16.57 27.467,16.57 28.367,16.57 18.437,16.726 0.89,16.78 1.881,16.858 4.881,16.858 7.881,16.858 9.381,16.858 10.881,16.858 12.381,16.858 45.08,17.218 46.08,17.218 47.08,17.218 48.08,17.218 49.08,17.218 50.08,17.218 51.08,17.218 52.08,17.218 53.08,17.218 54.08,17.218 1.239,17.284 24.767,17.47 25.667,17.47 26.567,17.47 27.467,17.47 28.367,17.47 40.376,17.577 41.376,17.577 43.376,17.577 45.576,17.567 46.576,17.567 47.576,17.567 48.576,17.567 49.576,17.567 50.576,17.567 51.576,17.567 52.584,17.567 53.576,17.567 54.584,17.567 42.313,17.581 33.2,17.725 39.673,17.733 0.89,17.78 40.872,17.926 42.872,17.926 45.08,17.917 46.08,17.917 47.08,17.917 48.08,17.917 49.08,17.917 50.08,17.917 51.08,17.917 52.08,17.917 53.08,17.917 54.08,17.917 55.08,17.917 43.583,18.159 1.239,18.284 34.376,18.276 35.376,18.276 36.376,18.276 37.376,18.276 38.376,18.276 39.376,18.276 40.376,18.276 58.54,18.287 57.68,18.306 56.618,18.316 2.631,18.358 4.131,18.358 5.631,18.358 7.131,18.358 8.631,18.358 10.131,18.358 11.631,18.358 13.131,18.358 55.565,18.393 41.971,18.463 42.971,18.463 18.518,18.487 56.106,18.712 57.12,18.721 58.173,18.721 58.925,18.725 33.169,18.753 0.89,18.78 34.1,18.8 34.927,18.799 35.927,18.799 36.927,18.799 37.927,18.799 38.927,18.799 39.927,18.799 41.475,18.813 42.475,18.813 43.475,18.813 40.717,18.835 55.575,19.221 56.575,19.221 57.575,19.221 58.575,19.221 1.239,19.284 39.478,19.321 34.683,19.489 35.683,19.489 36.683,19.489 37.683,19.489 38.683,19.489 58.925,19.725 0.89,19.78 1.881,19.858 4.881,19.858 7.881,19.858 9.381,19.858 10.881,19.858 12.381,19.858 15.381,19.858 33.381,19.858 40.881,19.858 42.381,19.858 46.881,19.858 48.381,19.858 49.881,19.858 51.381,19.858 52.881,19.858 57.004,19.977 58.575,20.221 1.239,20.284 58.925,20.725 0.89,20.78 18.585,21.161 58.575,21.221 1.239,21.284 8.631,21.358 10.131,21.358 11.631,21.358 13.131,21.358 16.131,21.358 34.131,21.358 35.631,21.358 37.131,21.358 38.631,21.358 40.131,21.358 41.631,21.358 43.131,21.358 46.131,21.358 47.631,21.358 49.131,21.358 50.631,21.358 52.131,21.358 53.631,21.358 30.942,21.658 29.816,21.698 58.925,21.725 0.89,21.78 30.446,22.008 31.446,22.008 32.446,22.008 33.446,22.008 1.239,22.284 2.4,22.3 30.942,22.358 31.942,22.358 32.942,22.358 33.942,22.358 33.438,22.707 58.925,22.725 0.89,22.78 1.881,22.858 4.881,22.858 7.881,22.858 9.381,22.858 10.881,22.858 12.381,22.858 15.381,22.858 18.381,22.858 36.381,22.858 37.881,22.858 39.381,22.858 40.881,22.858 42.381,22.858 45.381,22.858 46.881,22.858 48.381,22.858 49.881,22.858 51.381,22.858 52.881,22.858 54.381,22.858 55.881,22.858 57.381,22.858 34.255,22.894 58.575,23.221 1.239,23.284 58.925,23.725 0.89,23.78 20.228,23.967 58.575,24.221 1.239,24.284 8.631,24.358 10.131,24.358 11.631,24.358 13.131,24.358 16.131,24.358 34.131,24.358 35.631,24.358 37.131,24.358 38.631,24.358 40.131,24.358 46.131,24.358 47.631,24.358 49.131,24.358 50.631,24.358 52.131,24.358 53.631,24.358 55.131,24.358 56.631,24.358 41.936,24.55 58.925,24.725 0.89,24.78 23.806,24.942 2.418,25.218 1.239,25.284 23.51,25.532 24.089,25.532 58.925,25.725 0.89,25.78 1.881,25.858 4.881,25.858 7.881,25.858 9.381,25.858 10.881,25.858 12.381,25.858 13.881,25.858 18.381,25.858 34.881,25.858 36.381,25.858 37.881,25.858 39.381,25.858 45.381,25.858 46.881,25.858 48.381,25.858 49.881,25.858 51.381,25.858 52.881,25.858 54.381,25.858 55.881,25.858 57.381,25.858 58.575,26.221 25.141,26.259 1.239,26.284 41.715,26.355 20.243,26.592 58.925,26.725 0.89,26.78 23.75,26.8 58.575,27.221 1.239,27.284 2.631,27.358 5.631,27.358 7.131,27.358 8.631,27.358 10.131,27.358 11.631,27.358 13.131,27.358 17.631,27.358 35.631,27.358 37.131,27.358 43.131,27.358 44.631,27.358 46.131,27.358 49.131,27.358 50.631,27.358 52.131,27.358 53.631,27.358 55.131,27.358 56.631,27.358 38.25,27.6 48.191,27.609 58.925,27.725 0.89,27.78 24.1,27.95 39.969,28.035 26.85,28.05 31.5,28.05 33.2,28.15 1.239,28.284 58.925,28.725 0.89,28.78 1.881,28.858 3.381,28.858 6.381,28.858 9.381,28.858 10.881,28.858 18.381,28.858 34.881,28.858 36.381,28.858 39.381,28.858 42.381,28.858 45.381,28.858 46.881,28.858 52.881,28.858 54.381,28.858 55.881,28.858 57.381,28.858 21.094,29.02 58.575,29.221 29.4,29.25 1.239,29.284 38.184,29.644 58.925,29.725 0.89,29.78 58.575,30.221 1.239,30.284 2.631,30.358 41.631,30.358 44.631,30.358 55.131,30.358 56.631,30.358 31.65,30.4 58.925,30.725 0.89,30.78 2.4,31.25 1.239,31.284 58.925,31.725 0.89,31.78 3.556,31.779 6.381,31.858 13.881,31.858 39.381,31.858 46.881,31.858 55.881,31.858 57.381,31.858 2.54,32.23 58.575,32.221 1.239,32.284 1.965,32.533 58.925,32.725 0.89,32.78 58.353,32.891 1.494,33.13 2.494,33.13 3.494,33.13 4.494,33.13 5.494,33.13 6.494,33.13 7.494,33.13 8.494,33.13 9.494,33.13 10.494,33.13 11.494,33.13 12.494,33.13 13.494,33.13 14.494,33.13 15.494,33.13 16.494,33.13 17.494,33.13 18.494,33.13 50.494,33.13 51.494,33.13 52.494,33.13 53.729,33.125 54.729,33.125 55.729,33.125 56.729,33.125 57.729,33.125 53.225,33.475 54.225,33.475 55.225,33.475 56.225,33.475 57.225,33.475 58.225,33.475 58.901,33.465 0.99,33.48 1.99,33.48 2.99,33.48 3.99,33.48 4.99,33.48 5.99,33.48 6.99,33.48 7.99,33.48 8.99,33.48 9.99,33.48 10.99,33.48 11.99,33.48 12.99,33.48 13.99,33.48 14.99,33.48 15.99,33.48 16.99,33.48 17.99,33.48 18.99,33.48 19.99,33.48 20.99,33.48 21.99,33.48 22.99,33.48 23.99,33.48 24.99,33.48 25.99,33.48 26.99,33.48 27.99,33.48 28.99,33.48 29.99,33.48 30.99,33.48 31.99,33.48 32.99,33.48 33.99,33.48 34.99,33.48 35.99,33.48 36.99,33.48 37.99,33.48 38.99,33.48 39.99,33.48 40.99,33.48 41.99,33.48 42.99,33.48 43.99,33.48 44.99,33.48 45.99,33.48 46.99,33.48 47.99,33.48 48.99,33.48 49.99,33.48 50.99,33.48 51.99,33.48
NetC6_1: C6.1 C7.1 L1.2 U4.41 | length 9.2
  Top Layer w0.254: v1@18.38,15.84 22.28,15.84 ; v1@21.904,15.832 U4.41@22.698,15.832
  Bottom Layer w0.254: 17.484,15.75 17.573,15.84 v1(18.379,15.84) ; v1(21.991,15.859) 21.997,15.865 21.997,16.465 C7.1@22.091,16.559
  Bottom Layer w0.4: L1.2@16.186,15.288 17.021,15.288 17.484,15.75 C6.1@17.484,16.986
  Bottom Layer w0.5: L1.2@16.186,15.288 L1.2@16.238,15.34
NetC8_1: C8.1 U4.39 X1.2 | length 7.9
  Top Layer w0.254: X1.2@17.395,20.912 C8.1@17.395,22.261 ; X1.2@17.88,20.9 21.917,16.862 U4.39@22.8,16.862
NetC9_1: C9.1 U4.40 X1.1 | length 8
  Top Layer w0.254: X1.1@17.395,19.412 17.395,18.076 C9.1@17.44,18.03 ; X1.1@17.44,19.432 18.608,19.432 21.677,16.362 U4.40@22.8,16.362
NetC13_2: C13.2 C16.2 R2.1 U3.4 | length 5
  Top Layer w0.2: C16.2@44.267,14.537 44.267,15.892 U3.4@44.284,15.909
  Top Layer w0.4: C13.2@42.469,12.801 44.27,12.801 R2.1@44.27,13.138 44.27,14.534 C16.2@44.267,14.537 ; C13.2@42.469,12.801 C13.2@42.469,12.855
NetC15_1: C15.1 C18.2 L3.1 U4.24 | length 4.3
  Top Layer w0.3: U4.24@29.496,17.832 29.496,18.223 C15.1@30.428,19.155 ; C15.1@30.487,19.308 31.663,19.308 C18.2@31.672,19.317 31.672,18.807 L3.1@31.037,18.172
NetC19_1: C19.1 U3.1 | length 1.6
  Top Layer w0.7: C19.1@40.679,16.709 42.285,16.709
NetC19_2: C19.2 U1.6 | length 5.3
  Top Layer w0.2: U1.6@34.473,17.192 35.098,17.192
  Top Layer w0.7: 34.893,17.17 38.377,17.167 cw(c38.377,15.605) C19.2@39.481,16.709
NetC23_2: C23.2 C41.1 R3.1 U3.6 | length 4.9
  Top Layer w0.2: U3.6@44.284,16.709 44.403,16.828 C41.1@44.403,18.893 44.418,18.908 C23.2@44.418,20.293 44.418,21.574 R3.1@44.398,21.593
NetC25_1: C25.1 U3.5 | length 1.5
  Top Layer w0.2: U3.5@44.284,16.309 C25.1@45.799,16.309
NetC25_2: C25.2 C29.1 L7.1 | length 2.5
  Top Layer w0.7: C25.2@46.997,16.309 48.176,16.309 L7.1@49.48,16.309
NetC26_1: C26.1 C36.2 X2.1 | length 3.1
  Top Layer w0.2: X2.1@28.395,26.078 X2.1@28.585,26.078
  Top Layer w0.3: X2.1@28.585,26.078 30.111,26.078 C26.1@30.133,26.1 ; C26.1@30.205,26.172 C26.1@30.133,26.1 ; C36.2@31.385,26.1 C26.1@30.133,26.1
NetC27_2: C27.2 U1.4 U3.3 | length 9.5
  Top Layer w0.2: 34.478,15.295 U1.4@34.478,15.514 ; U3.3@43.304,15.895 43.304,15.897 43.317,15.909 U3.3@43.484,15.909
  Top Layer w0.7: C27.2@34.464,14.311 34.464,15.11 ; C27.2@34.569,14.31 41.385,14.31 ccw(c41.385,15.789) 42.43,14.743 42.659,14.972
NetC28_1: C28.1 J4.1 L7.2 | length 7
  Top Layer w0.7: L7.2@50.678,16.309 J4.1@57.7,16.309
NetC31_1: C31.1 SB15.2 X2.3 | length 2.8
  Top Layer w0.3: C31.1@25.918,24.738 C31.1@26.058,24.878 ; C31.1@25.973,24.878 C31.1@26.058,24.878 ; C31.1@26.263,24.878 C31.1@26.226,24.878 ; X2.3@27.235,24.878 C31.1@26.226,24.878 ; C31.1@26.058,24.878 C31.1@26.226,24.878
  Top Layer w0.4: SB15.2@27.2,23.7 27.2,24.993 X2.3@27.235,25.028
NetC36_1: C36.1 R100.2 | length 1.1
  Top Layer w0.3: R100.2@32.592,24.952 C36.1@32.592,26.1
NetC37_2: C37.2 L9.1 X2.2 | length 5.3
  Top Layer w0.4: C37.2@27.098,27.2 L9.1@31.2,27.2
  Top Layer w0.625: C37.2@27.098,27.2 27.098,26.215 X2.2@27.235,26.078
NetC200_1: C200.1 U1.1 | length 0.5
  Top Layer w0.28: C200.1@32.463,16.857 32.954,16.857
NetC200_2: C200.2 L3.2 U4.22 | length 2.5
  Top Layer w0.3: U4.22@29.474,16.831 30.601,16.831 30.599,16.833 C200.2@31.959,16.833
NetCN1_3: CN1.3 SB12.1 | length 2.2
  Bottom Layer w0.5: SB12.1@48.18,29.043 CN1.3@48.18,31.2
  Bottom Layer w0.6: SB12.1@48.18,29.043 SB12.1@48.216,29.006
NetCN1_5: CN1.5 SB10.1 | length 2.5
  Bottom Layer w0.5: CN1.5@43.1,31.2 43.1,30.916 43.758,30.257 43.758,29.235 43.783,29.21 SB10.1@43.783,29.005
NetL2_2: L2.2 U4.47 | length 2
  Top Layer w0.3: v1@21.919,12.18 21.958,12.218 21.958,12.348 22.361,12.752 22.468,12.752 22.548,12.832 U4.47@22.698,12.832
  Bottom Layer w0.4: L2.2@21.172,12.04 21.762,12.04 v1@21.939,12.217
  other v1: 21.891,12.209
NetR1_2: R1.2 SB11.1 | length 1.2
  Top Layer w0.5: SB11.1@34.725,10.919 R1.2@35.916,10.919
NetR2_2: R2.2 SB3.2 SB4.2 SB5.2 | length 4.2
  Top Layer w0.4: SB5.2@45.138,8.923 SB4.2@45.138,10.337 SB3.2@45.138,11.737 45.138,13.105 R2.2@45.17,13.138
NetR3_2: R3.2 SB6.2 SB9.2 | length 2.7
  Top Layer w0.2: R3.2@44.398,22.493 44.398,23.781 SB6.2@44.411,23.794 SB9.2@44.411,25.194
NetR100_1: R100.1 R101.1 SB13.2 | length 4
  Top Layer w0.3: SB13.2@28.7,23.7 30.965,23.7 31.141,23.876 31.141,23.954 31.237,24.05 R100.1@32.541,24.05
NetSB11_2: SB11.2 U4.19 | length 7.2
  Top Layer w0.15: U4.19@29.496,15.332 30.011,15.332 31.179,14.163 v1@31.179,13.68
  Top Layer w0.3: v1(33.291,10.909) 33.791,10.909
  Bottom Layer w0.2: v1(31.239,13.66) 31.239,12.232 32.562,10.909 v1(33.291,10.909)
NetSB13_1: SB13.1 U4.26 | length 4.5
  Top Layer w0.2: U4.26@28.358,18.482 28.358,21.638 28.7,21.98 SB13.1@28.7,22.8
NetSB15_1: SB15.1 U4.27 | length 4.6
  Top Layer w0.2: SB15.1@27.2,22.8 27.2,22.36 27.909,21.65 27.909,18.534 U4.27@27.858,18.482
NRST: C12.1 CN2.4 U2.1 U4.18 | length 24.5
  Top Layer w0.15: U4.18@29.496,14.832 30.065,14.832 30.764,14.132 30.764,13.375 32.755,11.385 32.755,9.325 v1@33.455,8.624 ; v1(33.441,8.609) 34.078,8.609 U2.1@34.087,8.6 34.087,9.574 C12.1@34.164,9.65 ; v1(41.919,5.778) 41.897,5.756 41.897,5.734 43.204,5.734 v2(44.16,4.778)
  Bottom Layer w0.15: v1@33.455,8.624 36.301,5.778 v1(41.919,5.778) ; v2(44.16,4.778) 45.64,3.299 CN2.4@45.64,3.2
PA0: CN2.14 U4.7 | length 11.8
  Top Layer w0.2: v1(24.56,8.58) 24.56,8.6 26.358,10.398 U4.7@26.358,11.685
  Bottom Layer w0.15: CN2.14@20.24,3.2 20.154,3.285 20.154,5.085 22.933,7.863 24.226,7.863 24.56,8.197 v1(24.56,8.58)
PA1: CN2.13 U4.8 | length 10.2
  Top Layer w0.2: v1(25.34,8.58) 25.38,8.58 26.858,10.058 U4.8@26.858,11.685
  Bottom Layer w0.15: CN2.13@22.78,3.2 22.78,5.722 25.34,8.282 v1(25.34,8.58)
PA2: CN2.12 U4.9 | length 9.3
  Top Layer w0.15: CN2.12@25.32,3.2 25.32,5.69 v1(25.748,6.118)
  Top Layer w0.2: v1@26.1,8.58 27.358,9.838 U4.9@27.358,11.685
  Bottom Layer w0.15: v1(25.748,6.118) 26.1,6.47 v1(26.1,8.51)
PA3: CN2.11 U4.10 | length 9.4
  Top Layer w0.15: v1(26.971,6.097) 27.86,5.208 CN2.11@27.86,3.2
  Top Layer w0.2: v1@26.8,8.56 27.858,9.618 U4.10@27.858,11.685
  Bottom Layer w0.15: v1(26.86,8.6) 26.86,6.208 v1(26.971,6.097)
PA4: CN2.10 U4.12 | length 10.2
  Top Layer w0.2: U4.12@28.858,11.685 29.275,11.685 29.386,11.573 29.992,11.573 v1(30.036,11.618)
  Bottom Layer w0.15: 29.9,9.491 29.9,5.471 30.418,4.953 30.418,3.218 CN2.10@30.4,3.2
  Bottom Layer w0.2: 29.9,9.491 30.325,9.917 30.325,11.329 v1(30.036,11.618) v1@30,11.581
